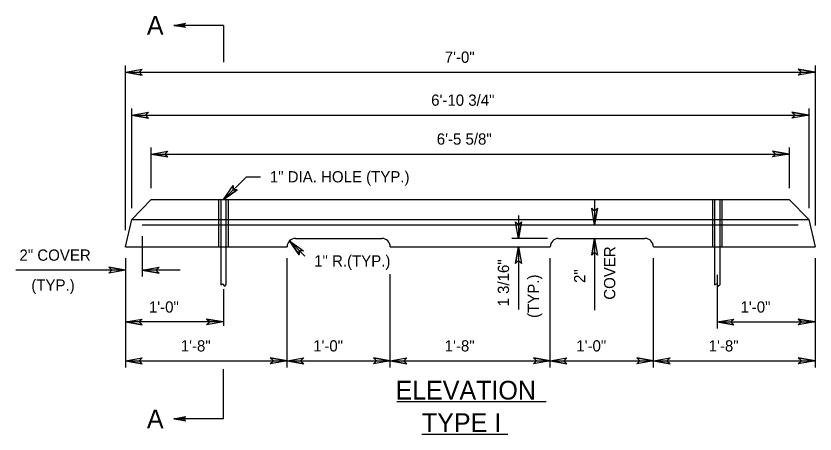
# Model space of a CAD drawing. Extents: x 12.4 to 19.6, y 6 to 16.2.
# Drawn here: x 12.472 to 16.741, y 13.984 to 16.216 of the extents above; entities that cross this region are included whole.
import ezdxf

# ---------------------------------------------------------------- set-up
doc = ezdxf.new("R2010")
doc.units = 0
for name, color, linetype in [('DETL-DIMS', 7, 'Continuous'), ('DETL-LINE', 7, 'Continuous'), ('DETL-NOTE', 7, 'Continuous'), ('DETL-TITL', 7, 'Continuous')]:
    doc.layers.add(name, color=color, linetype=linetype)

msp = doc.modelspace()

# ---------------------------------------------------------------- linework, layer by layer
at = {"layer": 'DETL-DIMS'}
for p, q in [((13.5797, 16.1657), (13.315, 16.1657)), ((13.5797, 16.1657), (13.5797, 15.9689)), ((13.0566, 15.0732), (13.0566, 15.9509)), ((13.0566, 15.9159), (13.146, 15.9316)), ((13.1291, 15.9159), (13.146, 15.9316)), ((16.741, 15.9159), (16.6516, 15.9316)), ((16.6516, 15.9316), (16.6685, 15.9159)), ((16.741, 15.9509), (16.741, 15.0966)), ((13.0566, 15.9159), (16.741, 15.9159)), ((13.0566, 15.9159), (13.146, 15.9001)), ((13.146, 15.9001), (13.1291, 15.9159)), ((16.741, 15.9159), (16.6516, 15.9001)), ((16.6685, 15.9159), (16.6516, 15.9001)), ((13.0903, 15.1892), (13.0903, 15.7215)), ((16.7072, 15.7215), (16.7072, 15.1892)), ((13.0903, 15.6865), (13.1797, 15.7022)), ((13.0903, 15.6865), (16.7072, 15.6865)), ((13.0903, 15.6865), (13.1797, 15.6707)), ((13.1628, 15.6865), (13.1797, 15.7022)), ((13.1797, 15.6707), (13.1628, 15.6865)), ((16.7072, 15.6865), (16.6178, 15.7022)), ((16.6178, 15.7022), (16.6347, 15.6865)), ((16.7072, 15.6865), (16.6178, 15.6707)), ((16.6347, 15.6865), (16.6178, 15.6707)), ((13.1943, 15.2961), (13.1943, 15.5139)), ((16.6031, 15.5139), (16.6031, 15.2961)), ((13.1943, 15.4789), (13.2837, 15.4946)), ((13.1943, 15.4789), (16.6031, 15.4789)), ((13.1943, 15.4789), (13.2837, 15.4631)), ((13.2668, 15.4789), (13.2837, 15.4946)), ((13.2837, 15.4631), (13.2668, 15.4789)), ((16.6031, 15.4789), (16.5137, 15.4946)), ((16.5137, 15.4946), (16.5306, 15.4789)), ((16.6031, 15.4789), (16.5137, 15.4631)), ((16.5306, 15.4789), (16.5137, 15.4631)), ((13.5797, 15.2361), (13.7025, 15.3574)), ((13.7025, 15.3574), (13.7781, 15.3574)), ((13.5797, 15.2361), (13.6322, 15.3101)), ((13.5797, 15.2361), (13.6543, 15.2877)), ((13.6313, 15.2871), (13.6322, 15.3101)), ((13.6543, 15.2877), (13.6313, 15.2871)), ((15.5635, 15.2359), (15.5635, 15.1011)), ((15.5635, 15.1011), (15.5477, 15.1905)), ((15.5635, 15.1736), (15.5477, 15.1905)), ((15.5635, 15.1011), (15.5792, 15.1905)), ((15.5792, 15.1905), (15.5635, 15.1736)), ((15.1561, 15.028), (15.1403, 15.1174)), ((15.1561, 15.1005), (15.1403, 15.1174)), ((15.1561, 15.1501), (15.1561, 15.028)), ((15.1561, 15.028), (15.1718, 15.1174)), ((15.1718, 15.1174), (15.1561, 15.1005)), ((13.1466, 15.0411), (13.1466, 14.8242)), ((13.9332, 15.0149), (14.0148, 14.9332)), ((13.9332, 15.0149), (13.9852, 14.9405)), ((13.9332, 15.0149), (14.0076, 14.9629)), ((15.3112, 15.028), (15.1211, 15.028)), ((15.5635, 15.028), (15.5477, 14.9386)), ((15.5635, 15.028), (15.5635, 14.6456)), ((15.5635, 15.028), (15.5792, 14.9386)), ((13.9852, 14.9405), (13.9845, 14.9636)), ((13.9845, 14.9636), (14.0076, 14.9629)), ((15.1561, 14.983), (15.1403, 14.8936)), ((15.1561, 14.983), (15.1561, 14.6497)), ((15.1561, 14.983), (15.1718, 14.8936)), ((15.5477, 14.9386), (15.5635, 14.9555)), ((15.5635, 14.9555), (15.5792, 14.9386)), ((13.0566, 14.923), (13.0566, 14.3397)), ((13.92, 14.3397), (13.92, 14.923)), ((15.1403, 14.8936), (15.1561, 14.9105)), ((15.1561, 14.9105), (15.1718, 14.8936)), ((15.3262, 14.3397), (15.3262, 14.923)), ((15.8775, 14.3397), (15.8775, 14.923)), ((16.741, 14.923), (16.741, 14.3397)), ((13.0566, 14.8592), (12.4716, 14.8592)), ((13.0566, 14.8592), (12.9672, 14.875)), ((12.9672, 14.875), (12.9841, 14.8592)), ((13.0566, 14.8592), (12.9672, 14.8435)), ((12.9841, 14.8592), (12.9672, 14.8435)), ((13.1466, 14.8592), (13.236, 14.875)), ((13.3491, 14.8592), (13.1466, 14.8592)), ((13.1466, 14.8592), (13.236, 14.8435)), ((13.2191, 14.8592), (13.236, 14.875)), ((13.236, 14.8435), (13.2191, 14.8592)), ((14.4712, 14.3397), (14.4712, 14.8366)), ((16.2178, 14.8335), (16.2178, 14.5472)), ((13.5797, 14.7577), (13.5797, 14.5615)), ((13.0566, 14.5822), (13.146, 14.598)), ((13.5797, 14.5822), (13.0566, 14.5822)), ((13.0566, 14.5822), (13.146, 14.5665)), ((13.1291, 14.5822), (13.146, 14.598)), ((13.146, 14.5665), (13.1291, 14.5822)), ((13.5797, 14.5822), (13.4903, 14.598)), ((13.4903, 14.598), (13.5072, 14.5822)), ((13.5797, 14.5822), (13.4903, 14.5665)), ((13.5072, 14.5822), (13.4903, 14.5665)), ((16.2178, 14.5822), (16.3072, 14.598)), ((16.2178, 14.5822), (16.741, 14.5822)), ((16.2178, 14.5822), (16.3072, 14.5665)), ((16.2903, 14.5822), (16.3072, 14.598)), ((16.3072, 14.5665), (16.2903, 14.5822)), ((16.741, 14.5822), (16.6516, 14.598)), ((16.6516, 14.598), (16.6685, 14.5822)), ((16.741, 14.5822), (16.6516, 14.5665)), ((16.6685, 14.5822), (16.6516, 14.5665)), ((13.0566, 14.3747), (13.146, 14.3905)), ((13.1291, 14.3747), (13.146, 14.3905)), ((13.92, 14.3747), (13.8306, 14.3905)), ((13.8306, 14.3905), (13.8475, 14.3747)), ((13.92, 14.3747), (14.0093, 14.3905)), ((13.9925, 14.3747), (14.0093, 14.3905)), ((14.4712, 14.3747), (14.3818, 14.3905)), ((14.3818, 14.3905), (14.3987, 14.3747)), ((14.4712, 14.3747), (14.5606, 14.3905)), ((14.5437, 14.3747), (14.5606, 14.3905)), ((15.3262, 14.3747), (15.2368, 14.3905)), ((15.2368, 14.3905), (15.2537, 14.3747)), ((15.3262, 14.3747), (15.4156, 14.3905)), ((15.3987, 14.3747), (15.4156, 14.3905)), ((15.8775, 14.3747), (15.7881, 14.3905)), ((15.7881, 14.3905), (15.805, 14.3747)), ((15.8775, 14.3747), (15.9668, 14.3905)), ((15.95, 14.3747), (15.9668, 14.3905)), ((16.741, 14.3747), (16.6516, 14.3905)), ((16.6516, 14.3905), (16.6685, 14.3747)), ((13.0566, 14.3747), (13.92, 14.3747)), ((13.0566, 14.3747), (13.146, 14.359)), ((13.146, 14.359), (13.1291, 14.3747)), ((13.92, 14.3747), (13.8306, 14.359)), ((13.8475, 14.3747), (13.8306, 14.359)), ((13.92, 14.3747), (14.4712, 14.3747)), ((13.92, 14.3747), (14.0093, 14.359)), ((14.0093, 14.359), (13.9925, 14.3747)), ((14.4712, 14.3747), (14.3818, 14.359)), ((14.3987, 14.3747), (14.3818, 14.359)), ((14.4712, 14.3747), (15.3262, 14.3747)), ((14.4712, 14.3747), (14.5606, 14.359)), ((14.5606, 14.359), (14.5437, 14.3747)), ((15.3262, 14.3747), (15.2368, 14.359)), ((15.2537, 14.3747), (15.2368, 14.359)), ((15.3262, 14.3747), (15.8775, 14.3747)), ((15.3262, 14.3747), (15.4156, 14.359)), ((15.4156, 14.359), (15.3987, 14.3747)), ((15.8775, 14.3747), (15.7881, 14.359)), ((15.805, 14.3747), (15.7881, 14.359)), ((15.8775, 14.3747), (16.741, 14.3747)), ((15.8775, 14.3747), (15.9668, 14.359)), ((15.9668, 14.359), (15.95, 14.3747)), ((16.741, 14.3747), (16.6516, 14.359)), ((16.6685, 14.3747), (16.6516, 14.359)), ((13.5797, 14.065), (13.5797, 14.3297)), ((13.5797, 14.065), (13.315, 14.065))]:
    msp.add_line(p, q, dxfattribs=at)
for points in [[(13.315, 16.1657), (13.3778, 16.1774), (13.373, 16.1741), (13.3705, 16.1699), (13.3698, 16.1657), (13.3705, 16.1614), (13.373, 16.1572), (13.3778, 16.1538), (13.315, 16.1657), (13.373, 16.1572), (13.3705, 16.1614), (13.315, 16.1657), (13.3698, 16.1657), (13.3705, 16.1699), (13.315, 16.1657), (13.373, 16.1741)], [(13.315, 14.065), (13.3778, 14.0769), (13.373, 14.0735), (13.3705, 14.0692), (13.3698, 14.065), (13.3705, 14.0609), (13.373, 14.0566), (13.3778, 14.0532), (13.315, 14.065), (13.373, 14.0566), (13.3705, 14.0609), (13.315, 14.065), (13.3698, 14.065), (13.3705, 14.0692), (13.315, 14.065), (13.373, 14.0735)]]:
    msp.add_lwpolyline(points, dxfattribs=at)
for points in [[(13.146, 15.9001), (13.0566, 15.9159), (13.146, 15.9316), (13.1291, 15.9159)], [(16.6516, 15.9316), (16.741, 15.9159), (16.6516, 15.9001), (16.6685, 15.9159)], [(13.1797, 15.6707), (13.0903, 15.6865), (13.1797, 15.7022), (13.1628, 15.6865)], [(16.6178, 15.7022), (16.7072, 15.6865), (16.6178, 15.6707), (16.6347, 15.6865)], [(13.2837, 15.4631), (13.1943, 15.4789), (13.2837, 15.4946), (13.2668, 15.4789)], [(16.5137, 15.4946), (16.6031, 15.4789), (16.5137, 15.4631), (16.5306, 15.4789)], [(13.6543, 15.2877), (13.5797, 15.2361), (13.6322, 15.3101), (13.6313, 15.2871)], [(15.5792, 15.1905), (15.5635, 15.1011), (15.5477, 15.1905), (15.5635, 15.1736)], [(15.1718, 15.1174), (15.1561, 15.028), (15.1403, 15.1174), (15.1561, 15.1005)], [(13.9852, 14.9405), (13.9332, 15.0149), (14.0076, 14.9629), (13.9845, 14.9636)], [(15.5477, 14.9386), (15.5635, 15.028), (15.5792, 14.9386), (15.5635, 14.9555)], [(15.1403, 14.8936), (15.1561, 14.983), (15.1718, 14.8936), (15.1561, 14.9105)], [(12.9672, 14.875), (13.0566, 14.8592), (12.9672, 14.8435), (12.9841, 14.8592)], [(13.236, 14.8435), (13.1466, 14.8592), (13.236, 14.875), (13.2191, 14.8592)], [(13.146, 14.5665), (13.0566, 14.5822), (13.146, 14.598), (13.1291, 14.5822)], [(13.4903, 14.598), (13.5797, 14.5822), (13.4903, 14.5665), (13.5072, 14.5822)], [(16.3072, 14.5665), (16.2178, 14.5822), (16.3072, 14.598), (16.2903, 14.5822)], [(16.6516, 14.598), (16.741, 14.5822), (16.6516, 14.5665), (16.6685, 14.5822)], [(13.146, 14.359), (13.0566, 14.3747), (13.146, 14.3905), (13.1291, 14.3747)], [(13.8306, 14.3905), (13.92, 14.3747), (13.8306, 14.359), (13.8475, 14.3747)], [(14.0093, 14.359), (13.92, 14.3747), (14.0093, 14.3905), (13.9925, 14.3747)], [(14.3818, 14.3905), (14.4712, 14.3747), (14.3818, 14.359), (14.3987, 14.3747)], [(14.5606, 14.359), (14.4712, 14.3747), (14.5606, 14.3905), (14.5437, 14.3747)], [(15.2368, 14.3905), (15.3262, 14.3747), (15.2368, 14.359), (15.2537, 14.3747)], [(15.4156, 14.359), (15.3262, 14.3747), (15.4156, 14.3905), (15.3987, 14.3747)], [(15.7881, 14.3905), (15.8775, 14.3747), (15.7881, 14.359), (15.805, 14.3747)], [(15.9668, 14.359), (15.8775, 14.3747), (15.9668, 14.3905), (15.95, 14.3747)], [(16.6516, 14.3905), (16.741, 14.3747), (16.6516, 14.359), (16.6685, 14.3747)]]:
    msp.add_lwpolyline(points, close=True, dxfattribs=at)
at = {"layer": 'DETL-LINE'}
for p, q in [((13.0903, 15.1292), (13.1943, 15.2361)), ((13.1943, 15.2361), (13.5543, 15.2361)), ((13.5543, 15.2361), (13.5543, 14.983)), ((13.5543, 15.2361), (13.605, 15.2361)), ((13.5656, 15.2361), (13.5656, 14.983)), ((13.5937, 15.2361), (13.5937, 14.983)), ((13.605, 15.2361), (13.605, 14.983)), ((13.605, 15.2361), (15.5381, 15.2361)), ((15.5381, 15.2361), (16.6031, 15.2361)), ((16.1925, 15.2361), (16.1925, 14.983)), ((16.2037, 15.2361), (16.2037, 14.983)), ((16.2318, 15.2361), (16.2318, 14.983)), ((16.2431, 15.2361), (16.2431, 14.983)), ((16.6031, 15.2361), (16.7072, 15.1292)), ((13.0566, 14.983), (13.0903, 15.1292)), ((13.0903, 15.1292), (15.1305, 15.1292)), ((15.1305, 15.1292), (15.5925, 15.1292)), ((15.5925, 15.1292), (16.7072, 15.1292)), ((16.7072, 15.1292), (16.741, 14.983)), ((13.1466, 15.1011), (15.1932, 15.1011)), ((15.1932, 15.1011), (16.651, 15.1011)), ((13.965, 15.028), (14.4262, 15.028)), ((15.3712, 15.028), (15.8325, 15.028)), ((13.0566, 14.983), (13.92, 14.983)), ((13.5656, 14.983), (13.5656, 14.7805)), ((13.5937, 14.983), (13.5937, 14.7805)), ((14.4712, 14.983), (15.3262, 14.983)), ((15.8775, 14.983), (16.741, 14.983)), ((16.2037, 14.983), (16.2037, 14.7805)), ((16.2318, 14.983), (16.2318, 14.7805))]:
    msp.add_line(p, q, dxfattribs=at)
for centre, start, end in [((13.965, 14.983), 90, 180), ((14.4262, 14.983), 0, 90), ((15.3712, 14.983), 90, 180), ((15.8325, 14.983), 0, 90)]:
    msp.add_arc(centre, 0.045, start, end, dxfattribs=at)
for points in [[(13.5656, 14.7805), (13.5761, 14.7857), (13.5858, 14.7739), (13.5937, 14.7805)], [(16.2037, 14.7805), (16.2142, 14.7857), (16.224, 14.7739), (16.2318, 14.7805)]]:
    msp.add_spline(points, degree=3, dxfattribs=at)
at = {"layer": 'DETL-TITL'}
for p, q in [((14.5057, 14.157), (15.3036, 14.157)), ((14.6405, 13.9842), (15.1002, 13.9842))]:
    msp.add_line(p, q, dxfattribs=at)

# ---------------------------------------------------------------- texts
at = {"layer": 'DETL-NOTE'}
for s, height, p in [('A', 0.1, (13.1711, 16.1157)), ('7\'-0"', 0.06, (14.7625, 15.9659)), ('6\'-10 3/4"', 0.06, (14.6901, 15.7365)), ('6\'-5 5/8"', 0.06, (14.72, 15.5289)), ('1" DIA. HOLE (TYP.)', 0.06, (13.8281, 15.3274)), ('2" COVER', 0.06, (12.4903, 14.9092)), ('1" R.(TYP.)', 0.06, (14.0648, 14.8782)), ('(TYP.)', 0.06, (12.5536, 14.7492)), ('1\'-0"', 0.06, (13.1819, 14.6322)), ('1\'-0"', 0.06, (16.3431, 14.6322)), ('1\'-8"', 0.06, (13.352, 14.4247)), ('1\'-0"', 0.06, (14.0593, 14.4247)), ('1\'-8"', 0.06, (14.7624, 14.4247)), ('1\'-0"', 0.06, (15.4655, 14.4247)), ('1\'-8"', 0.06, (16.1729, 14.4247)), ('A', 0.1, (13.1711, 14.015))]:
    msp.add_text(s, height=height, dxfattribs=at).set_placement(p)
for s, p in [('COVER', (15.6735, 14.7009)), ('1 3/16"', (15.1061, 14.6651)), ('2"', (15.5135, 14.7905)), ('(TYP.)', (15.2661, 14.6038))]:
    msp.add_text(s, height=0.06, rotation=90, dxfattribs=at).set_placement(p)
at = {"layer": 'DETL-TITL'}
for s, p in [('ELEVATION', (14.4992, 14.1681)), ('TYPE I', (14.6405, 13.9953))]:
    msp.add_text(s, height=0.1, dxfattribs=at).set_placement(p)

doc.saveas('drawing.dxf')
